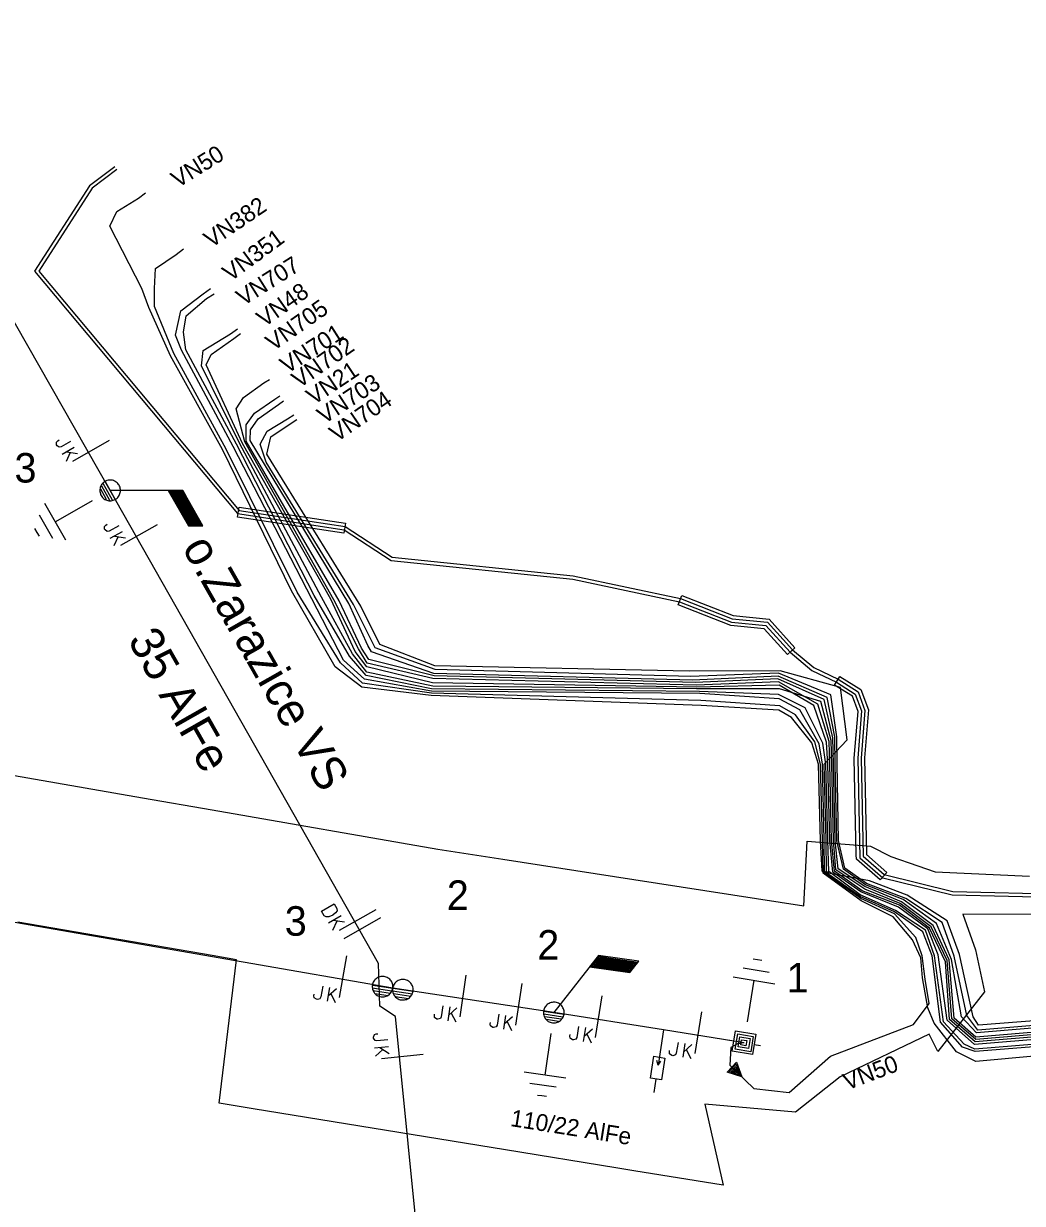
# Model space of a CAD drawing. Extents: x -545588 to -543214, y -1196037 to -1194452.
# Drawn here: x -545323.7 to -545264.5, y -1194915.7 to -1194845.7 of the extents above; entities that cross this region are included whole.
import ezdxf

# ---------------------------------------------------------------- set-up
doc = ezdxf.new("R2010")
doc.units = 0
for name, color, linetype in [('Default', 7, 'Continuous'), ('Vrstva 1', 7, 'Continuous'), ('Vrstva 11', 7, 'Continuous'), ('Vrstva 12', 7, 'Continuous'), ('Vrstva 13', 7, 'Continuous'), ('Vrstva 14', 7, 'Continuous'), ('Vrstva 15', 7, 'Continuous'), ('Vrstva 16', 7, 'Continuous'), ('Vrstva 18', 7, 'Continuous'), ('Vrstva 19', 7, 'Continuous'), ('Vrstva 2', 7, 'Continuous'), ('Vrstva 20', 7, 'Continuous'), ('Vrstva 35', 7, 'Continuous'), ('Vrstva 4', 7, 'Continuous'), ('Vrstva 5', 7, 'Continuous'), ('Vrstva 52', 7, 'Continuous'), ('Vrstva 53', 7, 'Continuous'), ('Vrstva 54', 7, 'Continuous'), ('Vrstva 7', 7, 'Continuous')]:
    doc.layers.add(name, color=color, linetype=linetype)

# ---------------------------------------------------------------- blocks, each defined once
blk = doc.blocks.new('VN850')
at = {"layer": 'Vrstva 15'}
for points in [[(-0.565, 1.426), (-0.565, -1.074)], [(-0.014, 1.426), (-0.014, -1.074)], [(-2.091, -0.542), (-1.776, -0.542)], [(-2.091, -1.409), (-2.091, -0.542)], [(-1.776, -0.542), (-1.657, -0.602)], [(-1.657, -0.602), (-1.588, -0.749)], [(-1.264, -0.542), (-1.264, -1.409)], [(-0.85, -0.542), (-1.264, -1.094)], [(-1.667, -1.35), (-1.776, -1.409)], [(-1.588, -1.202), (-1.667, -1.35)], [(-1.588, -0.749), (-1.549, -0.956)], [(-1.549, -0.956), (-1.588, -1.202)], [(-1.126, -0.917), (-0.772, -1.409)], [(-1.776, -1.409), (-2.091, -1.409)]]:
    blk.add_lwpolyline(points, dxfattribs=at)
blk = doc.blocks.new('VN840')
at = {"layer": 'Vrstva 15'}
for points in [[(-0.009, 1.414), (-0.009, -1.086)], [(-1.092, -0.594), (-1.092, -1.243)], [(-0.678, -0.594), (-0.678, -1.421)], [(-0.678, -1.106), (-0.265, -0.594)], [(-1.505, -1.243), (-1.505, -1.145)], [(-1.476, -1.352), (-1.505, -1.243)], [(-1.328, -1.421), (-1.476, -1.352)], [(-1.131, -1.352), (-1.269, -1.421)], [(-1.092, -1.243), (-1.131, -1.352)], [(-0.541, -0.938), (-0.196, -1.421)], [(-1.269, -1.421), (-1.328, -1.421)]]:
    blk.add_lwpolyline(points, dxfattribs=at)
blk = doc.blocks.new('VN440')
at = {"layer": 'Vrstva 2'}
for points in [[(1.22, 0), (1.21, 0.13), (1.19, 0.25), (1.16, 0.38), (1.11, 0.5), (1.05, 0.61), (0.98, 0.72), (0.9, 0.82), (0.81, 0.91), (0.71, 0.99), (0.6, 1.06), (0.49, 1.12), (0.37, 1.16), (0.25, 1.2), (0.12, 1.22), (-0.01, 1.22), (-0.14, 1.22), (-0.26, 1.2), (-0.39, 1.16), (-0.51, 1.12), (-0.62, 1.06), (-0.73, 0.99), (-0.83, 0.91), (-0.92, 0.82), (-1, 0.72), (-1.07, 0.61), (-1.13, 0.5), (-1.18, 0.38), (-1.21, 0.25), (-1.23, 0.13), (-1.24, 0), (-1.23, -0.13), (-1.21, -0.26), (-1.18, -0.38), (-1.13, -0.5), (-1.07, -0.62), (-1, -0.73), (-0.92, -0.83), (-0.83, -0.92), (-0.73, -1), (-0.62, -1.07), (-0.51, -1.13), (-0.39, -1.17), (-0.26, -1.2), (-0.14, -1.23), (-0.01, -1.23), (0.12, -1.23), (0.25, -1.2), (0.37, -1.17), (0.49, -1.13), (0.6, -1.07), (0.71, -1), (0.81, -0.92), (0.9, -0.83), (0.98, -0.73), (1.05, -0.62), (1.11, -0.5), (1.16, -0.38), (1.19, -0.26), (1.21, -0.13), (1.22, 0)], [(-1.24, 0), (1.22, 0)], [(-1.18, -0.34), (1.1, -0.34)], [(-1.01, -0.63), (0.97, -0.63)], [(-0.74, -0.92), (0.68, -0.92)]]:
    blk.add_lwpolyline(points, dxfattribs=at)
blk = doc.blocks.new('VN890')
at = {"layer": 'Vrstva 4'}
for points in [[(-0.409, 0.411), (0.411, 0.001)], [(-0.409, -0.409), (-0.409, 0.411)], [(0.411, 0.001), (-0.409, -0.409)], [(-0.345, 0.31), (0.265, -0.003), (-0.345, -0.296), (-0.345, 0.31)], [(-0.264, 0.204), (0.104, 0.001), (-0.264, -0.183), (-0.264, 0.204)], [(-0.193, 0.094), (-0.045, 0.004), (-0.193, -0.08), (-0.193, 0.094)], [(-0.158, -0.009), (-0.158, 0.03), (-0.129, 0.007), (-0.158, -0.009)]]:
    blk.add_lwpolyline(points, dxfattribs=at)
blk = doc.blocks.new('VN820')
at = {"layer": 'Vrstva 13'}
for points in [[(0.003, 0.002), (0.003, -2.105)], [(-0.322, -1.632), (0.338, -1.632)], [(-0.322, -2.951), (-0.322, -1.632)], [(0.003, -2.105), (-0.115, -1.859)], [(0.003, -2.105), (0.121, -1.859)], [(0.338, -1.632), (0.338, -2.951)], [(0.338, -2.951), (-0.322, -2.951)], [(0.003, -2.951), (0.003, -3.748)]]:
    blk.add_lwpolyline(points, dxfattribs=at)
blk = doc.blocks.new('VN810')
at = {"layer": 'Vrstva 14'}
for points in [[(0.004, -1.247), (0.004, -3.747)], [(1.254, -3.747), (-1.246, -3.747)], [(0.772, -4.367), (-0.803, -4.367)], [(0.004, -4.997), (-0.252, -4.997)], [(0.27, -4.997), (0.004, -4.997)]]:
    blk.add_lwpolyline(points, dxfattribs=at)
blk = doc.blocks.new('VN450')
at = {"layer": 'Vrstva 2'}
for points in [[(0, 0), (-0.01, 0.13), (-0.03, 0.25), (-0.06, 0.38), (-0.11, 0.5), (-0.16, 0.61), (-0.23, 0.72), (-0.31, 0.82), (-0.4, 0.91), (-0.5, 0.99), (-0.61, 1.06), (-0.72, 1.11), (-0.84, 1.16), (-0.97, 1.19), (-1.09, 1.21), (-1.22, 1.22), (-1.35, 1.21), (-1.47, 1.19), (-1.59, 1.16), (-1.71, 1.11), (-1.83, 1.06), (-1.93, 0.99), (-2.03, 0.91), (-2.12, 0.82), (-2.2, 0.72), (-2.27, 0.61), (-2.33, 0.5), (-2.38, 0.38), (-2.41, 0.25), (-2.43, 0.13), (-2.44, 0), (-2.43, -0.13), (-2.41, -0.25), (-2.38, -0.38), (-2.33, -0.5), (-2.27, -0.61), (-2.2, -0.72), (-2.12, -0.82), (-2.03, -0.91), (-1.93, -0.99), (-1.83, -1.06), (-1.71, -1.11), (-1.59, -1.16), (-1.47, -1.19), (-1.35, -1.21), (-1.22, -1.22), (-1.09, -1.21), (-0.97, -1.19), (-0.84, -1.16), (-0.72, -1.11), (-0.61, -1.06), (-0.5, -0.99), (-0.4, -0.91), (-0.31, -0.82), (-0.23, -0.72), (-0.16, -0.61), (-0.11, -0.5), (-0.06, -0.38), (-0.03, -0.25), (-0.01, -0.13), (0, 0)], [(-2.44, 0), (2.44, 0)], [(2.44, 0), (2.43, 0.13), (2.41, 0.25), (2.38, 0.38), (2.33, 0.5), (2.27, 0.61), (2.2, 0.72), (2.12, 0.82), (2.03, 0.91), (1.94, 0.99), (1.83, 1.06), (1.71, 1.11), (1.6, 1.16), (1.47, 1.19), (1.35, 1.21), (1.22, 1.22), (1.09, 1.21), (0.97, 1.19), (0.84, 1.16), (0.72, 1.11), (0.61, 1.06), (0.5, 0.99), (0.4, 0.91), (0.31, 0.82), (0.23, 0.72), (0.16, 0.61), (0.11, 0.5), (0.06, 0.38), (0.03, 0.25), (0.01, 0.13), (0, 0), (0.01, -0.13), (0.03, -0.25), (0.06, -0.38), (0.11, -0.5), (0.16, -0.61), (0.23, -0.72), (0.31, -0.82), (0.4, -0.91), (0.5, -0.99), (0.61, -1.06), (0.72, -1.11), (0.84, -1.16), (0.97, -1.19), (1.09, -1.21), (1.22, -1.22), (1.35, -1.21), (1.47, -1.19), (1.6, -1.16), (1.71, -1.11), (1.83, -1.06), (1.94, -0.99), (2.03, -0.91), (2.12, -0.82), (2.2, -0.72), (2.27, -0.61), (2.33, -0.5), (2.38, -0.38), (2.41, -0.25), (2.43, -0.13), (2.44, 0)], [(-2.4, -0.31), (-0.04, -0.31)], [(-2.26, -0.61), (-0.17, -0.61)], [(-2.01, -0.92), (-0.42, -0.92)], [(0.04, -0.31), (2.4, -0.31)], [(0.17, -0.61), (2.27, -0.61)], [(0.42, -0.92), (2.02, -0.92)]]:
    blk.add_lwpolyline(points, dxfattribs=at)
blk = doc.blocks.new('VN001')
at = {"layer": 'Default'}
for p, q in [((2.017, 3.531), (4.432, 3.531)), ((2.046, 3.581), (4.461, 3.581)), ((2.074, 3.631), (4.49, 3.631)), ((2.103, 3.681), (4.519, 3.681)), ((2.132, 3.731), (2.543, 3.731)), ((1.732, 3.031), (4.144, 3.031)), ((1.76, 3.081), (4.173, 3.081)), ((1.789, 3.131), (4.201, 3.131)), ((1.817, 3.181), (4.23, 3.181)), ((1.846, 3.231), (4.259, 3.231)), ((1.874, 3.281), (4.288, 3.281)), ((1.903, 3.331), (4.317, 3.331)), ((1.932, 3.381), (4.346, 3.381)), ((1.96, 3.431), (4.375, 3.431)), ((1.989, 3.481), (4.403, 3.481))]:
    blk.add_line(p, q, dxfattribs=at)
blk.add_lwpolyline([(2.132, 3.732), (0, 0)], dxfattribs=at)
blk.add_lwpolyline([(4.545, 3.727), (2.132, 3.732), (1.705, 2.984), (4.117, 2.985)], close=True, dxfattribs=at)
blk = doc.blocks.new('VN470')
at = {"layer": 'Vrstva 2'}
for points in [[(0, 1.22), (0, 1.97)], [(-1.23, 1.22), (1.23, 1.22)], [(-1.23, -1.23), (-1.23, 1.22)], [(-0.92, 0.9), (0.92, 0.9)], [(-0.92, -0.95), (-0.92, 0.9)], [(-0.61, 0.61), (0.61, 0.61)], [(-0.61, -0.62), (-0.61, 0.61)], [(-0.31, -0.27), (-0.31, 0.34)], [(-0.31, 0.34), (0.31, 0.34)], [(0.31, 0.34), (0.31, -0.27)], [(0.61, 0.61), (0.61, -0.62)], [(0.92, 0.9), (0.92, -0.95)], [(1.23, 1.22), (1.23, -1.23)], [(1.23, -1.23), (-1.23, -1.23)], [(0.92, -0.95), (-0.92, -0.95)], [(0.61, -0.62), (-0.61, -0.62)], [(0.31, -0.27), (-0.31, -0.27)], [(0, -1.23), (0, -1.98)]]:
    blk.add_lwpolyline(points, dxfattribs=at)

msp = doc.modelspace()

# ---------------------------------------------------------------- linework, layer by layer
at = {"layer": 'Vrstva 1'}
for points in [[(-545292.23, -1194904.36), (-545301.79, -1194902.92), (-545381.67, -1194889.04), (-545464.66, -1194874.97), (-545546.4, -1194860.3), (-545587.311, -1194845.749)], [(-545280.96, -1194906.15), (-545285.729, -1194905.392), (-545292.23, -1194904.36)]]:
    msp.add_lwpolyline(points, dxfattribs=at)
at = {"layer": 'Vrstva 20'}
for points in [[(-545310.985, -1194874.997), (-545310.894, -1194874.403), (-545304.595, -1194875.363), (-545304.686, -1194875.957)], [(-545284.859, -1194880.199), (-545284.641, -1194879.641), (-545281.609, -1194880.826), (-545279.475, -1194881.043), (-545277.938, -1194882.738), (-545278.382, -1194883.142), (-545279.765, -1194881.617), (-545281.751, -1194881.414)], [(-545273.703, -1194895.001), (-545272.493, -1194896.054), (-545272.887, -1194896.506), (-545274.297, -1194895.279), (-545274.302, -1194895.013), (-545274.42, -1194889.281), (-545274.194, -1194886.512), (-545274.526, -1194885.62), (-545275.589, -1194884.954), (-545275.271, -1194884.446), (-545274.034, -1194885.22), (-545273.586, -1194886.428), (-545273.821, -1194889.269)]]:
    msp.add_lwpolyline(points, close=True, dxfattribs=at)
at = {"layer": 'Vrstva 35'}
for points in [[(-545337.5, -1194888.01), (-545316.63, -1194891.63), (-545312.5, -1194892.35), (-545299.12, -1194894.67), (-545295.27, -1194895.27), (-545287.5, -1194896.47), (-545277.41, -1194898.04), (-545277.21, -1194894.2), (-545273.46, -1194894.5), (-545272.25, -1194895.11), (-545270.66, -1194895.66), (-545269.62, -1194896.02), (-545264.03, -1194896.28)], [(-545262.5, -1194898.55), (-545267.99, -1194898.54), (-545267.228, -1194900.65), (-545266.71, -1194903.14), (-545269.47, -1194906.68), (-545269.99, -1194905.64), (-545275.25, -1194908.18), (-545277.91, -1194910.26), (-545283.29, -1194909.8), (-545282.67, -1194912.5), (-545282.19, -1194914.6), (-545287.5, -1194913.74), (-545288.56, -1194913.56), (-545295.11, -1194912.5), (-545310.07, -1194910.07), (-545312.09, -1194909.74), (-545311.05, -1194901.24), (-545312.5, -1194900.99), (-545324.01, -1194899.01)]]:
    msp.add_lwpolyline(points, dxfattribs=at)
at = {"layer": 'Vrstva 5'}
for points in [[(-545318.26, -1194854.24), (-545319.764, -1194855.371), (-545323.024, -1194860.428), (-545310.992, -1194874.793), (-545304.676, -1194875.756), (-545301.884, -1194877.567), (-545291.116, -1194878.669), (-545284.779, -1194880.016), (-545281.704, -1194881.218), (-545279.668, -1194881.426), (-545278.229, -1194883.012), (-545276.934, -1194884.085), (-545275.478, -1194884.788), (-545274.362, -1194885.487), (-545273.991, -1194886.484), (-545274.22, -1194889.287), (-545274.099, -1194895.186), (-545272.737, -1194896.371), (-545268.613, -1194897.38), (-545261.946, -1194897.55)], [(-545318.145, -1194854.404), (-545319.616, -1194855.509), (-545322.776, -1194860.412), (-545310.888, -1194874.607), (-545304.604, -1194875.564), (-545301.816, -1194877.373), (-545291.084, -1194878.471), (-545284.721, -1194879.824), (-545281.656, -1194881.022), (-545279.572, -1194881.234), (-545278.091, -1194882.868), (-545276.826, -1194883.915), (-545275.382, -1194884.612), (-545274.198, -1194885.353), (-545273.789, -1194886.456), (-545274.02, -1194889.293), (-545273.901, -1194895.094), (-545272.643, -1194896.189), (-545268.587, -1194897.18), (-545261.954, -1194897.35)], [(-545280.96, -1194906.15), (-545281.35, -1194906.22), (-545281.75, -1194906.44), (-545281.81, -1194907.48), (-545281.387, -1194907.886), (-545280.37, -1194908.87), (-545278.28, -1194909.1), (-545275.84, -1194906.95), (-545270.91, -1194905.07), (-545269.976, -1194903.823), (-545270.22, -1194902.39), (-545270.39, -1194901.01), (-545270.78, -1194899.92), (-545272.04, -1194898.52), (-545274.027, -1194897.61), (-545276.335, -1194895.985), (-545276.42, -1194894.18), (-545276.54, -1194889.64), (-545276.94, -1194888.38), (-545278.14, -1194886.88), (-545278.89, -1194886.45), (-545283.5, -1194886.17), (-545299.51, -1194885.57), (-545303.63, -1194885.07), (-545305.21, -1194883.88), (-545307.79, -1194879.36), (-545311.89, -1194871), (-545314.97, -1194865.44), (-545316.25, -1194862.58), (-545316.66, -1194861.44), (-545318.56, -1194857.75), (-545318.14, -1194856.88), (-545316.87, -1194856.09), (-545316.451, -1194855.779)], [(-545248.61, -1194905.57), (-545267.22, -1194907.27), (-545268.37, -1194906.69), (-545269.69, -1194905), (-545270.056, -1194904.082), (-545270.38, -1194902.31), (-545270.48, -1194901.12), (-545270.97, -1194900.05), (-545272.12, -1194898.68), (-545274.02, -1194897.75), (-545276.27, -1194896.11), (-545276.316, -1194894.192), (-545276.428, -1194889.638), (-545276.771, -1194888.321), (-545277.91, -1194886.71), (-545278.84, -1194886.18), (-545283.52, -1194885.86), (-545299.484, -1194885.433), (-545303.58, -1194884.84), (-545304.89, -1194883.64), (-545307.45, -1194879.44), (-545311.66, -1194870.97), (-545314.76, -1194865.31), (-545315.91, -1194862.52), (-545315.92, -1194861.44), (-545315.86, -1194860.26), (-545314.64, -1194859.43), (-545314.186, -1194859.097)], [(-545248.72, -1194905.18), (-545267.26, -1194906.67), (-545268, -1194906.41), (-545269.32, -1194904.93), (-545269.81, -1194901), (-545270.36, -1194899.57), (-545272.04, -1194898.4), (-545274.071, -1194897.475), (-545276.184, -1194896.005), (-545276.201, -1194894.148), (-545276.316, -1194889.638), (-545276.51, -1194888.43), (-545277.65, -1194886.42), (-545278.88, -1194885.77), (-545283.582, -1194885.46), (-545299.484, -1194885.308), (-545303.47, -1194884.61), (-545304.7, -1194883.47), (-545311.25, -1194870.82), (-545314.32, -1194865.11), (-545314.67, -1194864.22), (-545314.35, -1194862.78), (-545313.03, -1194861.76), (-545312.597, -1194861.441)], [(-545248.71, -1194905.01), (-545267.267, -1194906.539), (-545267.9, -1194906.24), (-545269.129, -1194904.91), (-545269.67, -1194901.01), (-545270.198, -1194899.48), (-545271.97, -1194898.314), (-545274.08, -1194897.377), (-545275.94, -1194896.01), (-545275.983, -1194894.152), (-545276.116, -1194889.638), (-545276.28, -1194888.4), (-545277.33, -1194886.3), (-545278.91, -1194885.52), (-545283.6, -1194885.327), (-545299.49, -1194885.17), (-545303.37, -1194884.38), (-545304.36, -1194883.24), (-545306.44, -1194879.65), (-545311.05, -1194870.68), (-545314.05, -1194865.09), (-545314.2, -1194864.03), (-545314.03, -1194863.06), (-545312.84, -1194862.05), (-545312.379, -1194861.759)], [(-545248.73, -1194904.4), (-545267.223, -1194905.96), (-545268.63, -1194904.731), (-545268.916, -1194901.286), (-545269.859, -1194899.284), (-545271.71, -1194897.9), (-545273.79, -1194897.04), (-545275.509, -1194895.899), (-545275.66, -1194894.15), (-545275.76, -1194889.647), (-545275.796, -1194888.232), (-545276.399, -1194885.93), (-545278.863, -1194885.175), (-545283.778, -1194885.175), (-545299.41, -1194885.02), (-545303.33, -1194884.18), (-545304.18, -1194883.1), (-545306.02, -1194879.74), (-545310.87, -1194870.61), (-545313.129, -1194866.04), (-545313.03, -1194865.13), (-545311.41, -1194864.14), (-545310.989, -1194863.845)], [(-545248.71, -1194904.72), (-545267.29, -1194906.26), (-545268.92, -1194904.81), (-545269.44, -1194900.94), (-545270.064, -1194899.408), (-545271.8, -1194898.11), (-545274.04, -1194897.2), (-545275.7, -1194896.04), (-545275.876, -1194894.165), (-545275.996, -1194889.643), (-545276.063, -1194888.347), (-545276.815, -1194886.164), (-545278.872, -1194884.953), (-545283.76, -1194885.07), (-545299.43, -1194884.82), (-545303.32, -1194883.88), (-545304.01, -1194882.97), (-545305.45, -1194879.87), (-545310.7, -1194870.63), (-545312.86, -1194865.98), (-545312.55, -1194865.37), (-545311.22, -1194864.41), (-545310.81, -1194864.123)], [(-545248.68, -1194904.56), (-545267.25, -1194906.09), (-545268.77, -1194904.77), (-545269.023, -1194901.357), (-545269.966, -1194899.355), (-545271.75, -1194898), (-545273.96, -1194897.15), (-545275.589, -1194895.975), (-545275.769, -1194894.17), (-545275.867, -1194889.647), (-545275.912, -1194888.298), (-545276.584, -1194886.092), (-545278.916, -1194884.757), (-545283.795, -1194884.953), (-545299.42, -1194884.56), (-545303.3, -1194883.65), (-545303.81, -1194882.81), (-545305.28, -1194879.91), (-545310.56, -1194870.54), (-545311.07, -1194868.58), (-545310.64, -1194867.91), (-545309.43, -1194867.05), (-545309.101, -1194866.84)], [(-545248.73, -1194904.26), (-545267.223, -1194905.818), (-545268.497, -1194904.695), (-545268.8, -1194901.233), (-545269.753, -1194899.204), (-545271.62, -1194897.81), (-545273.79, -1194896.9), (-545275.38, -1194895.84), (-545275.555, -1194894.192), (-545275.653, -1194889.647), (-545275.689, -1194888.08), (-545276.21, -1194885.807), (-545278.95, -1194884.58), (-545283.83, -1194884.81), (-545299.34, -1194884.41), (-545303.2, -1194883.43), (-545303.65, -1194882.76), (-545304.96, -1194879.97), (-545310.48, -1194870.49), (-545310.47, -1194869.52), (-545309.98, -1194868.83), (-545308.78, -1194868), (-545308.485, -1194867.803)], [(-545248.8, -1194904.02), (-545267.18, -1194905.57), (-545268.07, -1194904.61), (-545268.66, -1194901.21), (-545269.54, -1194899.09), (-545271.53, -1194897.66), (-545273.76, -1194896.79), (-545275.07, -1194895.87), (-545275.457, -1194894.179), (-545275.546, -1194889.656), (-545275.582, -1194888.027), (-545276.031, -1194885.692), (-545278.94, -1194884.43), (-545283.99, -1194884.66), (-545299.36, -1194884.26), (-545303.04, -1194882.99), (-545303.27, -1194882.6), (-545304.4, -1194880.12), (-545310.24, -1194870.45), (-545310.23, -1194869.82), (-545309.76, -1194869.17), (-545308.57, -1194868.32), (-545308.257, -1194868.111)], [(-545248.86, -1194903.88), (-545267.1, -1194905.41), (-545267.75, -1194904.54), (-545268.5, -1194901.02), (-545269.22, -1194899.03), (-545271.359, -1194897.6), (-545273.69, -1194896.71), (-545274.99, -1194895.81), (-545275.36, -1194894.17), (-545275.44, -1194889.63), (-545275.449, -1194888.027), (-545275.82, -1194885.54), (-545278.92, -1194884.25), (-545284.13, -1194884.44), (-545299.28, -1194884.04), (-545302.83, -1194882.74), (-545304.12, -1194880.18), (-545309.29, -1194871.74), (-545309.64, -1194870.67), (-545309.23, -1194869.91), (-545308.02, -1194869.17), (-545307.661, -1194868.936)], [(-545248.84, -1194903.69), (-545267.05, -1194905.12), (-545267.37, -1194904.62), (-545268.19, -1194900.93), (-545268.92, -1194898.92), (-545271.28, -1194897.4), (-545273.52, -1194896.55), (-545275.957, -1194896.094), (-545276.077, -1194895.999), (-545276.085, -1194894.152), (-545276.214, -1194889.643), (-545274.84, -1194888.2), (-545275.24, -1194885.1), (-545278.81, -1194884.1), (-545284.21, -1194884.13), (-545299.29, -1194883.82), (-545302.55, -1194882.54), (-545303.68, -1194880.28), (-545309.26, -1194871.27), (-545309.01, -1194870.25), (-545307.81, -1194869.43), (-545307.472, -1194869.214)]]:
    msp.add_lwpolyline(points, dxfattribs=at)
at = {"layer": 'Vrstva 52'}
for points in [[(-545318.54, -1194873.42), (-545325.567, -1194861.127)], [(-545295.62, -1194964.82), (-545301.623, -1194904.598), (-545302.546, -1194903.992), (-545302.625, -1194901.45), (-545318.54, -1194873.42)]]:
    msp.add_lwpolyline(points, dxfattribs=at)

# ---------------------------------------------------------------- block references
at = {"layer": 'Vrstva 11'}
for p, rotation in [((-545318.54, -1194873.419), -60.245422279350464), ((-545292.231, -1194904.361), -8.254969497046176)]:
    msp.add_blockref('VN001', p, dxfattribs=dict(at, rotation=rotation))
at = {"layer": 'Vrstva 13'}
for name, p, xscale, yscale, rotation in [('VN440', (-545318.541, -1194873.421), 0.5, 0.5, -60.248344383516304), ('VN450', (-545301.791, -1194902.92), 0.49999999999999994, 0.49999999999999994, -8.512510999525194), ('VN440', (-545292.231, -1194904.361), 0.5, 0.4999999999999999, -8.256972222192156), ('VN470', (-545280.96, -1194906.151), 0.5, 0.5000000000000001, 80.65912772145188)]:
    msp.add_blockref(name, p, dxfattribs=dict(at, xscale=xscale, yscale=yscale, rotation=rotation))
at = {"layer": 'Vrstva 15'}
for p, rotation in [((-545318.539, -1194873.42), -60.24428055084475), ((-545280.96, -1194906.15), 170.7505444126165), ((-545292.23, -1194904.36), -8.264269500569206)]:
    msp.add_blockref('VN810', p, dxfattribs=dict(at, rotation=rotation))
at = {"layer": 'Vrstva 16', "rotation": -9.029133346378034}
msp.add_blockref('VN820', (-545285.729, -1194905.392), dxfattribs=at)
at = {"layer": 'Vrstva 18'}
for name, p, rotation in [('VN840', (-545319.829, -1194871.164), -60.24658609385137), ('VN840', (-545316.984, -1194876.162), -60.412235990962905), ('VN850', (-545303.749, -1194899.47), -60.412235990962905), ('VN840', (-545304.766, -1194902.402), -9.857330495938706), ('VN840', (-545297.647, -1194903.544), -8.565930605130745), ('VN840', (-545294.339, -1194904.042), -8.56593047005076), ('VN840', (-545289.599, -1194904.778), -9.024833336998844), ('VN840', (-545283.703, -1194905.715), -9.02483334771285), ('VN840', (-545301.382, -1194907.004), -84.3081111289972)]:
    msp.add_blockref(name, p, dxfattribs=dict(at, rotation=rotation))
at = {"layer": 'Vrstva 19', "rotation": -43.88652780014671}
msp.add_blockref('VN890', (-545281.388, -1194907.886), dxfattribs=at)

# ---------------------------------------------------------------- texts
at = {"layer": 'Vrstva 12'}
msp.add_text('2', height=1.75, dxfattribs=at).set_placement((-545298.581, -1194898.279))
at = {"layer": 'Vrstva 14'}
for s, p in [('3', (-545324.216, -1194872.95)), ('3', (-545308.19, -1194899.81)), ('2', (-545293.217, -1194901.225)), ('1', (-545278.43, -1194903.167))]:
    msp.add_text(s, height=1.75, dxfattribs=at).set_placement(p)
at = {"layer": 'Vrstva 2'}
msp.add_text('110/22 AlFe', height=1, rotation=350.98, dxfattribs=at).set_placement((-545294.852, -1194911.085))
at = {"layer": 'Vrstva 53'}
msp.add_text('35 AlFe', height=2, rotation=299.588, dxfattribs=at).set_placement((-545317.535, -1194882.287))
at = {"layer": 'Vrstva 54'}
msp.add_text('o.Zarazice VS', height=2, rotation=299.588, dxfattribs=at).set_placement((-545314.315, -1194876.802))
at = {"layer": 'Vrstva 7'}
for s, rotation, p in [('VN50', 31.884, (-545314.532, -1194855.515)), ('VN382', 34.229, (-545312.556, -1194859.078)), ('VN351', 36.38, (-545311.413, -1194861.076)), ('VN707', 32.262, (-545310.659, -1194862.516)), ('VN48', 35.019, (-545309.415, -1194863.776)), ('VN705', 34.992, (-545308.876, -1194865.197)), ('VN701', 32.55, (-545308.06, -1194866.531)), ('VN702', 34.67, (-545307.338, -1194867.394)), ('VN21', 33.732, (-545306.484, -1194868.387)), ('VN703', 33.097, (-545305.852, -1194869.515)), ('VN704', 34.346, (-545305.109, -1194870.587)), ('VN50', 20.874, (-545274.846, -1194908.982))]:
    msp.add_text(s, height=1, rotation=rotation, dxfattribs=at).set_placement(p)

doc.saveas('drawing.dxf')
